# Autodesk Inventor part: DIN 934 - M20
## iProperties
Created: 2006-02
Part Number: DIN 934 - M20
Material: Steel, Mild
Description: Hex Nut
Document SubType Name: Modeling
Standard: DIN 934
Designer: Andy Moles
Standards Organization: DIN
Language: en-US
Size Designation: M20
Categories: <MemberInstance><Categories><Category DisplayName="Fasteners" InternalName="e4da775c-781d-43d5-af7c-5136215cf5a6" Mnemonic="FSTN"><Category DisplayName="Nuts" I
Density: 1 g/cm^3
Author: Andy Moles
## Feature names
1. Body [Extrusion]
2. Chamfer1 [Revolution]
3. Thread [Hole]
4. Chamfer2
5. Chamfer3
